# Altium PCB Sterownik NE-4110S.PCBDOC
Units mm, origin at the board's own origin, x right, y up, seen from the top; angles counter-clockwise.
Board outline 196.88 x 218.02 mm, 2 copper layers (TopLayer, BottomLayer); 94 components, 0 nets, 428 pads, 14 vias.
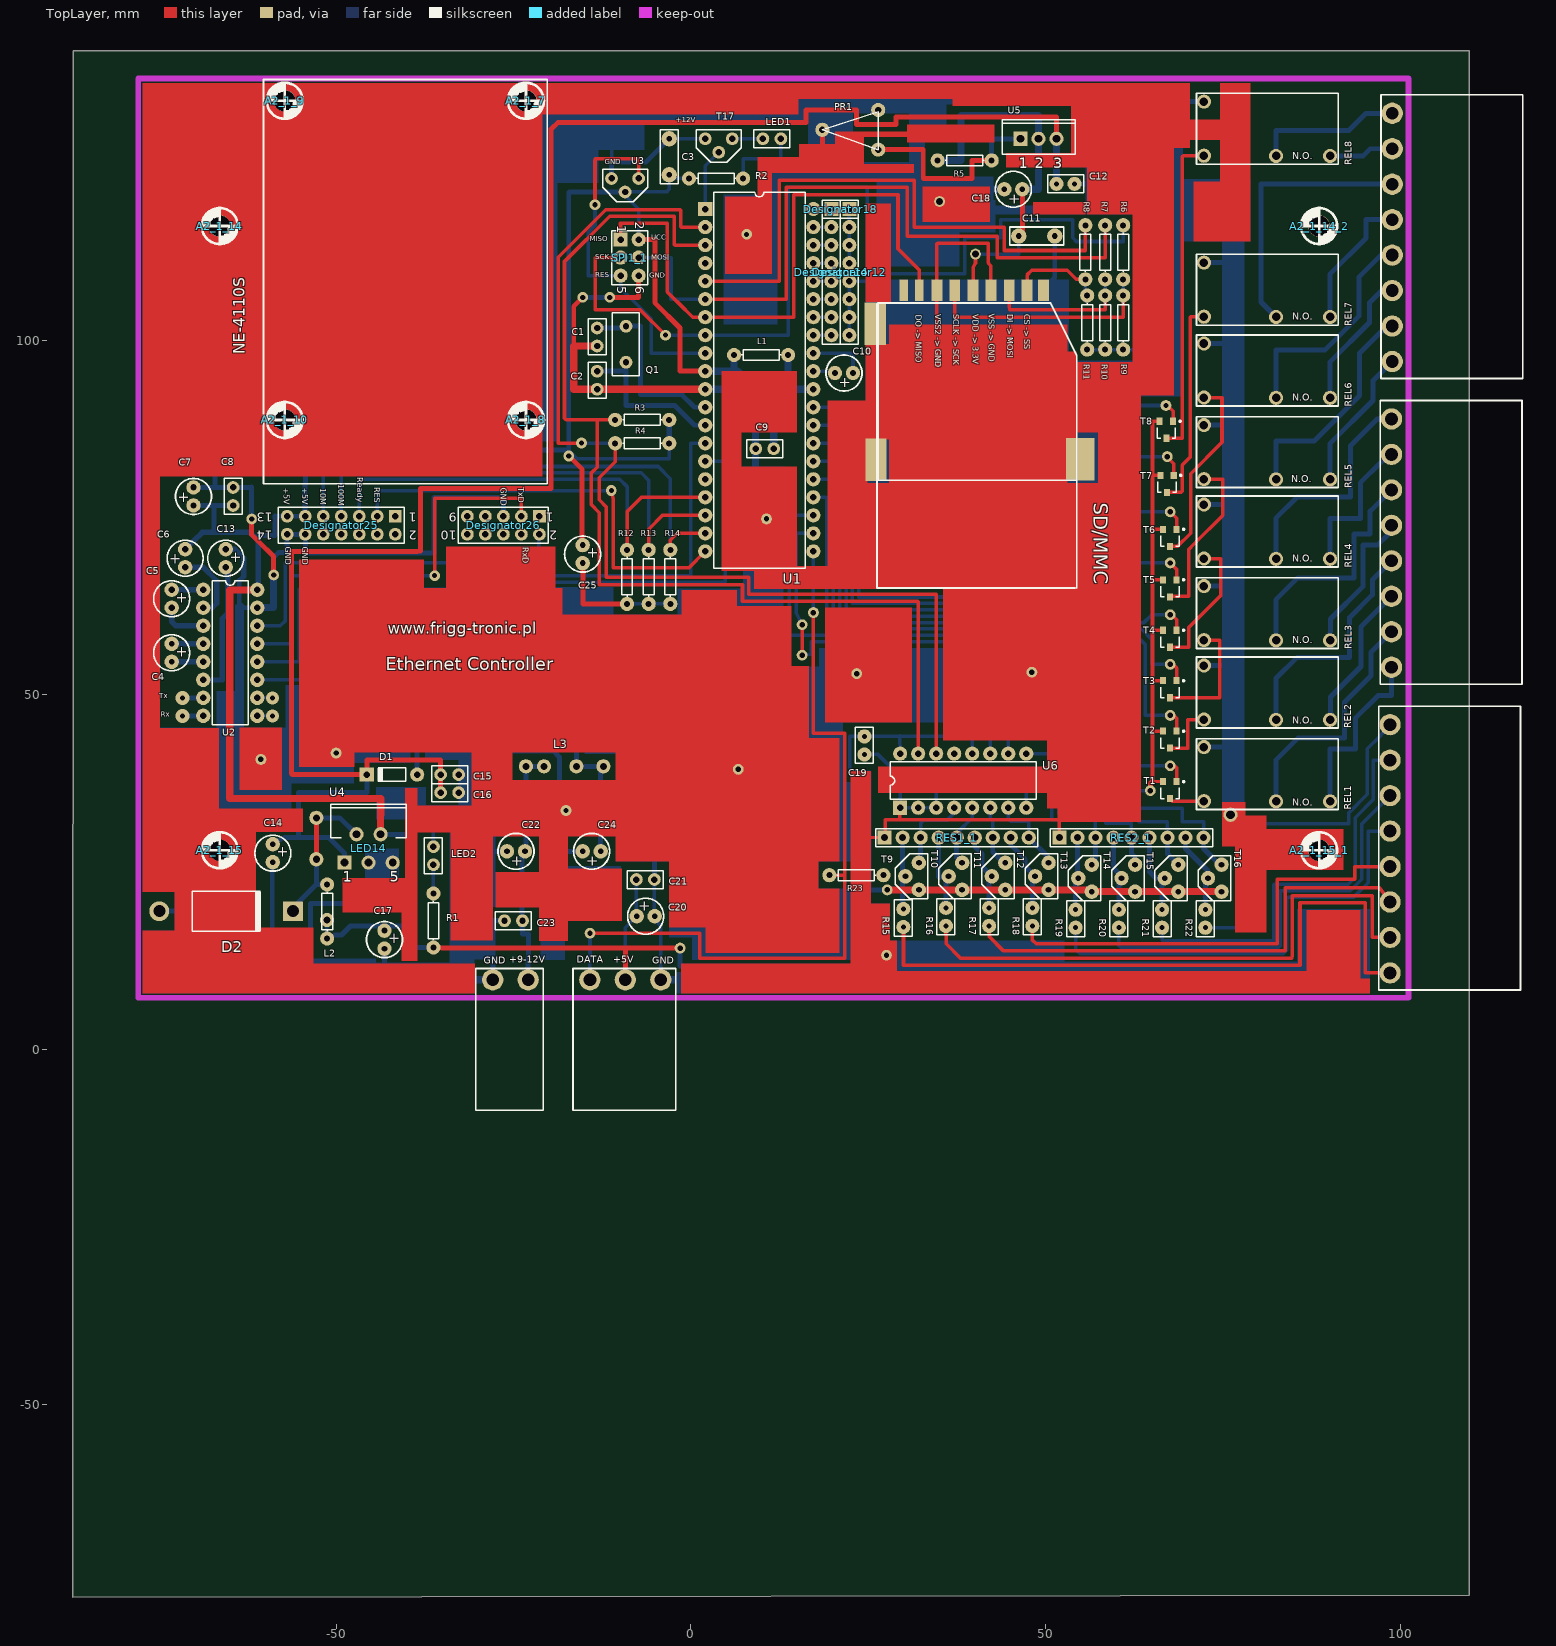
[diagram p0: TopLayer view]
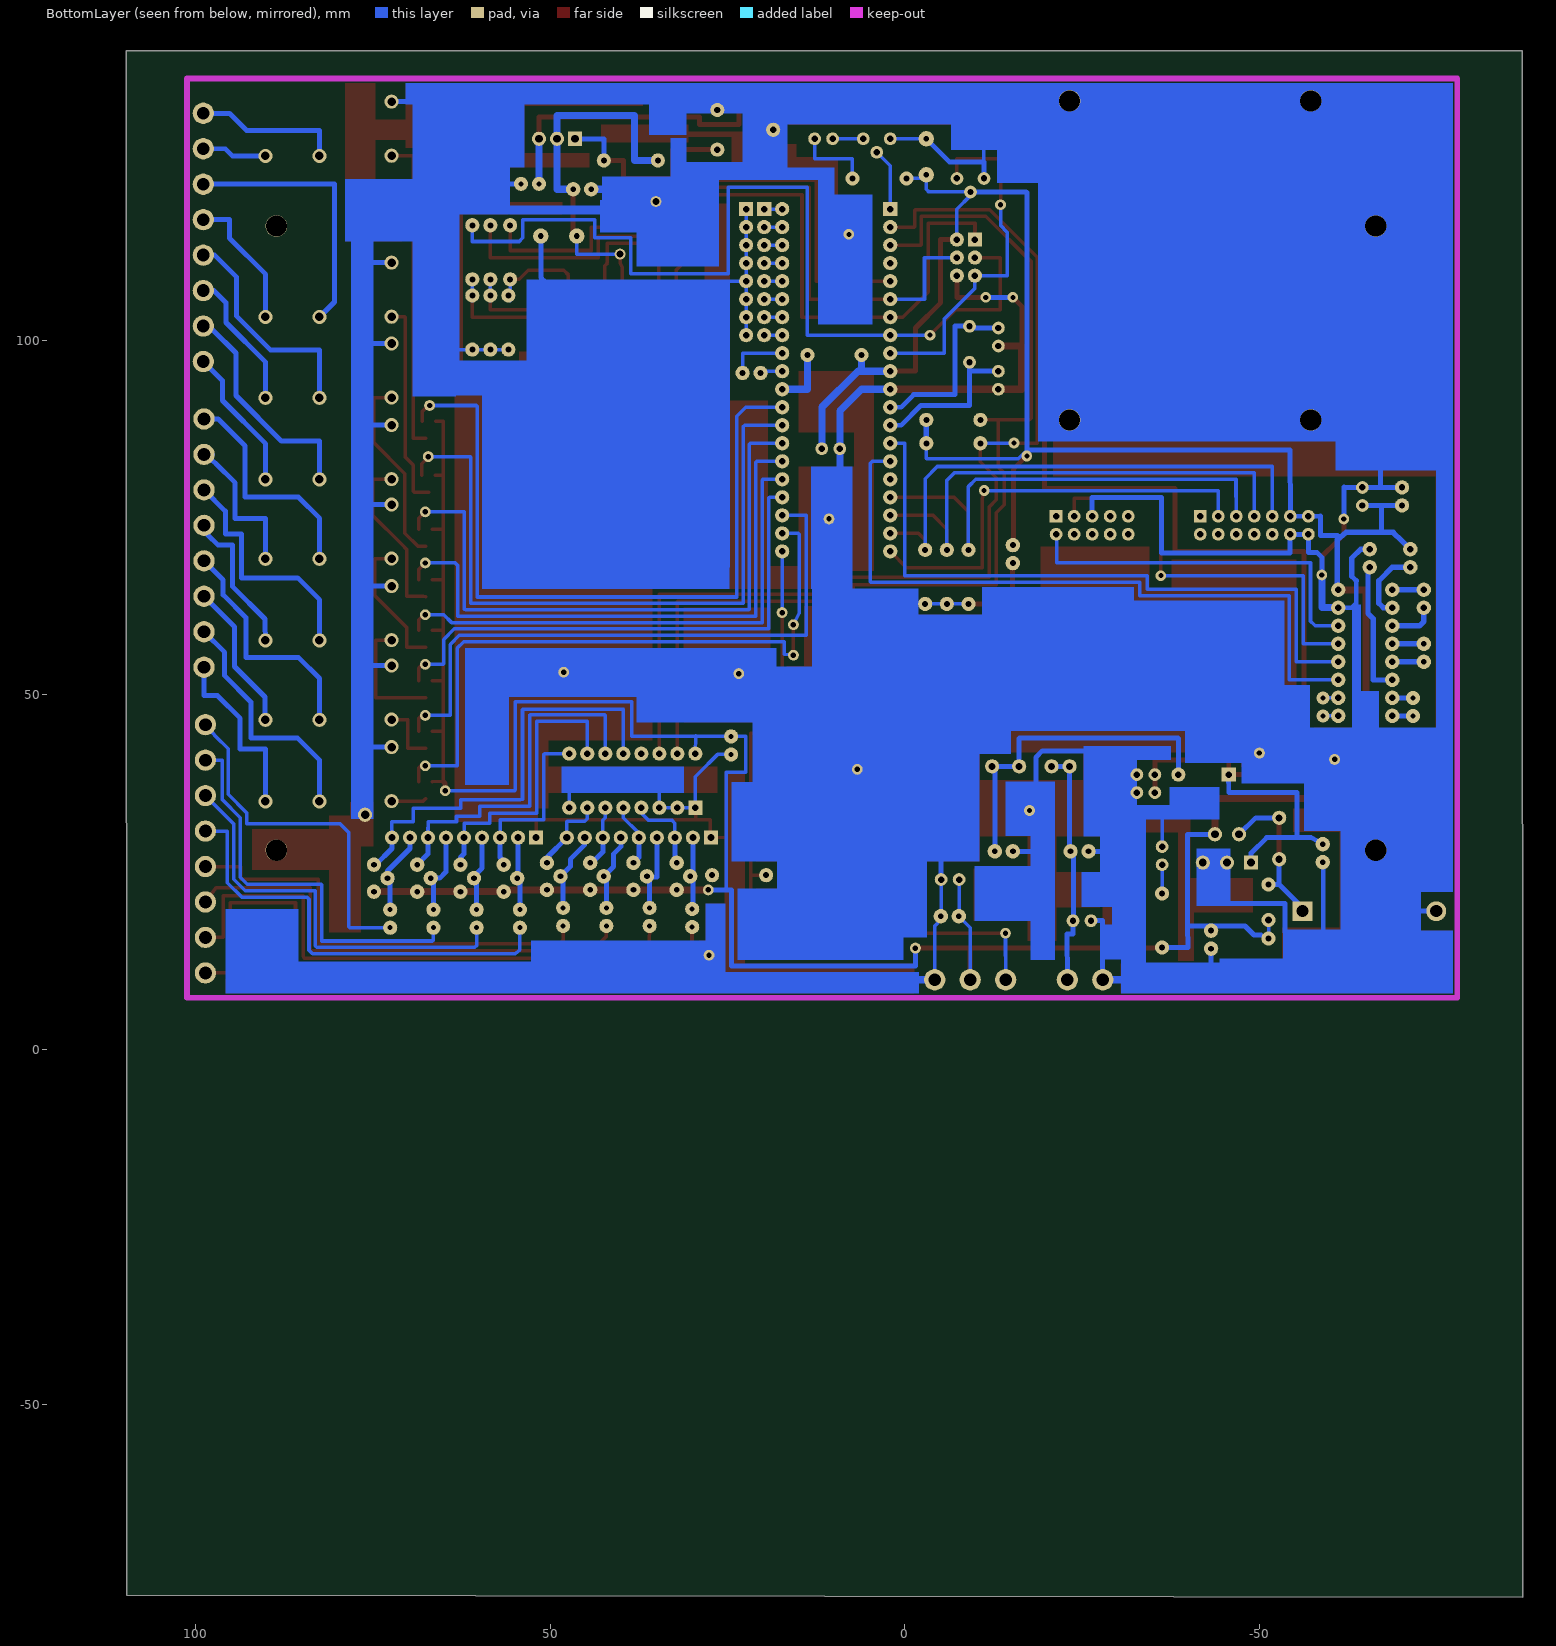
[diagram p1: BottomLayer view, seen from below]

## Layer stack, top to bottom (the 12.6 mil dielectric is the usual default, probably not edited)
TopLayer: signal copper 0.0356
Dielectric: core 0.32, FR-4, Dk 4.8
BottomLayer: signal copper 0.0356

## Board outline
-87.122,-77.216 109.728,-76.962 109.754,140.808 -87.046,140.808

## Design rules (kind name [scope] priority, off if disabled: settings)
Clearance [All] p1: gap=1
ComponentClearance [All] p1: gap=0.254 collisioncheckmode=0
PasteMaskExpansion PasteMaskExpansion_1 [All] p2: expansion=0
PlaneClearance PlaneClearance_1 [All] p1: clearance=0.508
PlaneClearance [All] p2: clearance=0.254
PolygonConnect [All] p1: connectstyle=Relief reliefconductorwidth=0.254 reliefentries=4 polygonreliefangle="90 Angle"
RoutingVias [All] p1: holewidth=1 width=3 viastyle="Through Hole" minholewidth=0.711 minwidth=1.27 maxholewidth=0.711 maxwidth=1.27
ShortCircuit ShortCircuit_1 [All] p2: allowed=FALSE
SolderMaskExpansion SolderMaskExpansion_1 [All] p1: expansion=0.102
SolderMaskExpansion [All] p2: expansion=0.051
TestPointUsage [All] p1: valid=0 allowmultiple=FALSE
Testpoint [All] p1: side=7 testpointundercomponent=TRUE minsize=1.016 maxsize=2.54 preferedsize=1.524 minholesize=0.508 maxholesize=1.016 preferedholesize=0.813 testpointgrid=0.025 style=1001 order=-539222988
UnRoutedNet UnRoutedNet_1 [All] p2:
Width [All] p1: maxlimit=0.8 minlimit=0.7 preferedwidth=0.254 toplayer_maxwidth=0.7 toplayer_prefwidth=0.7 bottomlayer_maxwidth=0.7 bottomlayer_prefwidth=0.5 minimp=50.000000 maximp=50.000000 favimp=50.000000
16 further rules are at their usual default settings.

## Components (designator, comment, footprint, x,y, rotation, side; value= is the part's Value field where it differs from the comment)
A2_1_7 "" S2 -23.24,133.76 r270 top
A2_1_8 "" S2 -23.24,88.76 r270 top
A2_1_9 "" S2 -57.24,133.76 r270 top
A2_1_10 "" S2 -57.24,88.76 r270 top
A2_1_14 "" S2 -66.4,116.1 r270 top
A2_1_14_2 "" S2 88.6,116.1 r270 top
A2_1_15 "" S2 -66.4,28.1 r270 top
A2_1_15_1 "" S2 88.6,28.1 r270 top
C1 "Comment" RAD-0.1#1 -13.194,101.73 r270 top
C2 "Comment" RAD-0.1#1 -13.194,95.634 r270 top
C3 "1u" C2 -3.034,123.32 r90 top
C4 "" CE5#1 -73.178,57.203 r270 top
C5 "" CE5#2 -73.178,64.823 r270 top locked
C6 "" CE5#3 -71.273,67.998 r270 top
C7 "" CE5#2 -70.104,76.708 r90 top
C8 "Comment" RAD-0.1#1 -64.516,76.708 r90 top
C9 "Comment" RAD-0.1#1 11.698,84.712 r180 top
C10 "" CE5#4 22.874,95.38 r0 top
C11 "1u" C2 46.242,114.684 r0 top
C12 "Comment" RAD-0.1#2 54.116,122.05 r180 top
C13 "" CE5#2 -65.558,70.538 r270 top locked
C14 "" CE5#1 -58.928,28.956 r270 top
C15 "Comment" RAD-0.1#1 -32.722,38.762 r180 top
C16 "Comment" RAD-0.1#1 -32.722,36.222 r180 top
C17 "" CE5#1 -43.18,16.764 r270 top
C18 "" CE5#1 46.75,121.288 r180 top
C19 "Comment" RAD-0.1#2 24.484,41.604 r90 top
C20 "" CE5#1 -7.62,18.796 r0 top
C21 "Comment" RAD-0.1#1 -5.122,23.962 r180 top
C22 "" CE5#1 -23.368,27.94 r180 top
C23 "Comment" RAD-0.1#1 -23.722,18.162 r180 top
C24 "" CE5#1 -12.7,27.94 r180 top
C25 "" CE5#1 -15.24,71.12 r270 top
D1 "Comment" DIO7.1-3.9x1.9 -42.12,38.762 r180 top
D2 "Comment" DIO18.84-9.6x5.6 -65.508,19.504 r0 top
Designator12 "Comment" HDR1X8 22.366,118.494 r270 top
Designator14 "Comment" HDR1X8 19.826,118.494 r270 top
Designator18 "Comment" HDR1X2 22.366,118.494 r180 top
Designator25 "Comment" HDR2X7 -41.656,75.184 r180 top
Designator26 "Comment" HDR2X5 -21.336,75.184 r180 top
L1 "Comment" AXIAL-0.3 9.92,97.92 r180 top
L2 "Comment" AXIAL-0.3 -51.264,19.458 r90 top
LED1 "Comment" RAD-0.1#1 12.714,128.4 r180 top
LED2 "Comment" RAD-0.1#1 -36.278,26.062 r90 top
LED14 "Comment" T05D -45.422,28.348 r0 top
Q1 "Comment" RAD-0.2 -9.13,101.978 r270 top
R1 "Comment" AXIAL-0.3 -36.278,18.188 r90 top
R2 "Comment" AXIAL-0.3 3.57,122.812 r180 top
R3 "Comment" AXIAL-0.3 -6.844,88.776 r180 top
R4 "Comment" AXIAL-0.3 -6.844,85.474 r180 top
R5 "Comment" AXIAL-0.3 38.622,125.352 r0 top
R6 "Comment" AXIAL-0.3 60.974,112.398 r270 top
R7 "Comment" AXIAL-0.3 58.434,112.398 r270 top
R8 "Comment" AXIAL-0.3 55.64,112.398 r270 top
R9 "Comment" AXIAL-0.3 60.974,102.492 r270 top
R10 "Comment" AXIAL-0.3 58.434,102.492 r270 top
R11 "Comment" AXIAL-0.3 55.894,102.492 r270 top
R12 "Comment" AXIAL-0.3 -8.976,66.636 r270 top
R13 "Comment" AXIAL-0.3 -5.928,66.636 r270 top
R14 "Comment" AXIAL-0.3 -2.88,66.636 r270 top
R15 "Comment" RAD-0.1#2 29.972,19.812 r270 top
R16 "Comment" RAD-0.1#2 35.976,17.43 r90 top
R17 "Comment" RAD-0.1#2 42.072,17.43 r90 top
R18 "Comment" RAD-0.1#2 48.168,17.43 r90 top
R19 "Comment" RAD-0.1#2 54.264,17.176 r90 top
R20 "Comment" RAD-0.1#2 60.36,17.176 r90 top
R21 "Comment" RAD-0.1#2 66.456,17.176 r90 top
R22 "Comment" RAD-0.1#2 72.552,17.176 r90 top
R23 "Comment" AXIAL-0.3 23.356,24.576 r180 top
RES1_1 "Comment" HDR1X9 27.34,29.876 r0 top
RES2_1 "Comment" HDR1X9 51.978,29.876 r0 top
SPI1_1 "Comment" HDR2X3 -9.886,114.192 r270 top
T1 "Comment" SOT23 67.564,36.576 r180 top
T2 "Comment" SOT23 67.564,43.688 r180 top
T3 "Comment" SOT23 67.564,50.8 r180 top
T4 "Comment" SOT23 67.564,57.912 r180 top
T5 "Comment" SOT23 67.564,65.024 r180 top
T6 "Comment" SOT23 67.564,72.136 r180 top
T7 "Comment" SOT23 67.15,79.756 r180 top
T8 "Comment" SOT23 67.056,87.376 r180 top
T9 "" T#1 32.166,26.32 r270 top
T10 "" T#1 38.262,26.32 r270 top
T11 "" T#1 44.358,26.32 r270 top
T12 "" T#1 50.454,26.32 r270 top
T13 "" T#1 56.55,26.066 r270 top
T14 "" T#1 62.646,26.066 r270 top
T15 "" T#1 68.742,26.066 r270 top
T16 "" T#1 74.838,26.066 r270 top
T17 "" T#2 2.046,128.4 r0 top
U1 "Comment" DIP-40/D53 9.666,94.364 r270 top
U2 "" U16 -68.733,64.823 r270 top locked
U3 "" T#2 -11.162,122.812 r0 top
U5 "Comment" SFM-T3/X1.6V 49.036,128.4 r0 top
U6 "Comment" DIP-16 38.414,37.906 r0 top

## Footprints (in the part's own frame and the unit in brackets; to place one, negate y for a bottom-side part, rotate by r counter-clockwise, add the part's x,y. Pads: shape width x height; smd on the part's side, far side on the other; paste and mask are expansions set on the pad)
AXIAL-0.3 [mm]
  round 2 hole 0.85: 1(-3.81,0) 2(3.81,0)
  silkscreen extent -2.77,-0.76 2.77,0.76
C2 [mil]
  round 85 hole 32: 1(0,0) 2(200,0)
  silkscreen extent -50,-50 250,50
CE5#1 [mil]
  round 80 hole 32: 1(0,0) 2(100,0)
  silkscreen extent -50,-100 150,100
CE5#2 [mil]
  round 80 hole 35.43: 1(0,0) 2(100,0)
  silkscreen extent -50,-100 150,100
CE5#3 [mil]
  round 80 hole 35.43: 1(0,0) 2(-100,0)
  silkscreen extent -150,-100 50,100
CE5#4 [mil]
  round 80 hole 32: 1(0,0) 2(-100,0)
  silkscreen extent -150,-100 50,100
DIO7.1-3.9x1.9 [mm]
  round 2 hole 0.9: 1(-3.55,0)
  rect 2x2 hole 0.9: 2(3.55,0)
  silkscreen extent -1.95,-0.95 2.05,0.95
DIO18.84-9.6x5.6 [mm]
  round 2.8 hole 1.7: 1(-9.42,0)
  rect 2.8x2.8 hole 1.7: 2(9.42,0)
  silkscreen extent -4.8,-2.8 4.9,2.8
DIP-16 [mm]
  rect 2x2 hole 0.9: 1(-8.89,-3.81)
  round 2 hole 0.9: 2(-6.35,-3.81) 3(-3.81,-3.81) 4(-1.27,-3.81) 5(1.27,-3.81) 6(3.81,-3.81) 7(6.35,-3.81) 8(8.89,-3.81) 9(8.89,3.81) 10(6.35,3.81) 11(3.81,3.81) 12(1.27,3.81) 13(-1.27,3.81) 14(-3.81,3.81) 15(-6.35,3.81) 16(-8.89,3.81)
  silkscreen extent -10.3,-2.65 10.3,2.65
DIP-40/D53 [mm]
  rect 2x2 hole 0.9: 1(-24.13,-7.62)
  round 2 hole 0.9: 2(-21.59,-7.62) 3(-19.05,-7.62) 4(-16.51,-7.62) 5(-13.97,-7.62) 6(-11.43,-7.62) 7(-8.89,-7.62) 8(-6.35,-7.62) 9(-3.81,-7.62) 10(-1.27,-7.62) 11(1.27,-7.62) 12(3.81,-7.62) 13(6.35,-7.62) 14(8.89,-7.62) 15(11.43,-7.62) 16(13.97,-7.62) 17(16.51,-7.62) 18(19.05,-7.62) 19(21.59,-7.62) 20(24.13,-7.62) 21(24.13,7.62) 22(21.59,7.62) 23(19.05,7.62) 24(16.51,7.62) 25(13.97,7.62) 26(11.43,7.62) 27(8.89,7.62) 28(6.35,7.62) 29(3.81,7.62) 30(1.27,7.62) 31(-1.27,7.62) 32(-3.81,7.62) 33(-6.35,7.62) 34(-8.89,7.62) 35(-11.43,7.62) 36(-13.97,7.62) 37(-16.51,7.62) 38(-19.05,7.62) 39(-21.59,7.62) 40(-24.13,7.62)
  silkscreen extent -26.5,-6.45 26.5,6.45
HDR1X2 [mm] "Connector; Header; 2 Position"
  rect 1.5x1.5 hole 0.9: 1(0,0)
  round 1.5 hole 0.9: 2(2.54,0)
  silkscreen extent -1.27,-1.27 3.81,1.27
HDR1X8 [mm] "Connector; Header; 8 Position"
  rect 2x2 hole 0.9: 1(0,0)
  round 2 hole 0.9: 2(2.54,0) 3(5.08,0) 4(7.62,0) 5(10.16,0) 6(12.7,0) 7(15.24,0) 8(17.78,0)
  silkscreen extent -1.27,-1.27 19.05,1.27
HDR1X9 [mm] "Connector; Header; 9 Position"
  rect 2x2 hole 1: 1(0,0)
  round 2 hole 1: 2(2.54,0) 3(5.08,0) 4(7.62,0) 5(10.16,0) 6(12.7,0) 7(15.24,0) 8(17.78,0) 9(20.32,0)
  silkscreen extent -1.27,-1.27 21.59,1.27
HDR2X3 [mm]
  rect 2x2 hole 0.9: 1(0,0)
  round 2 hole 0.9: 2(0,2.54) 3(2.54,0) 4(2.54,2.54) 5(5.08,0) 6(5.08,2.54)
  silkscreen extent -1.27,-1.27 6.35,3.81
HDR2X5 [mm] "Connector; Header; 5x2 Position"
  rect 1.8x1.8 hole 0.9: 1(0,0)
  round 1.8 hole 0.9: 2(0,2.54) 3(2.54,0) 4(2.54,2.54) 5(5.08,0) 6(5.08,2.54) 7(7.62,0) 8(7.62,2.54) 9(10.16,0) 10(10.16,2.54)
  silkscreen extent -1.27,-1.27 11.43,3.81
HDR2X7 [mm] "Connector; Header; 7x2 Position"
  rect 1.8x1.8 hole 0.9: 1(0,0)
  round 1.8 hole 0.9: 2(0,2.54) 3(2.54,0) 4(2.54,2.54) 5(5.08,0) 6(5.08,2.54) 7(7.62,0) 8(7.62,2.54) 9(10.16,0) 10(10.16,2.54) 11(12.7,0) 12(12.7,2.54) 13(15.24,0) 14(15.24,2.54)
  silkscreen extent -1.27,-1.27 16.51,3.81
RAD-0.1#1 [mm]
  round 1.8 hole 0.9: 1(0,0) 2(2.54,0)
  silkscreen extent -1.27,-1.27 3.81,1.27
RAD-0.1#2 [mm]
  round 2 hole 0.7: 1(0,0) 2(2.54,0)
  silkscreen extent -1.27,-1.27 3.81,1.27
RAD-0.2 [mm]
  round 1.8 hole 0.9: 1(0,0) 2(5.08,0)
  silkscreen extent -1.91,-1.91 6.98,1.91
S2 [mil]
  round 120 hole 117: 0(0,0)
  silkscreen extent -100,-100 100,100
SFM-T3/X1.6V [mm]
  rect 2x2 hole 1.1: 1(-2.54,0)
  round 2 hole 1.1: 2(0,0) 3(2.54,0)
  silkscreen extent -5.15,-2.2 5.15,2.7
SOT23 [mm] "SOT-23; 3 Leads; Body 3.0 x 2.5 mm, inc. leads (LxW max)"
  rect 0.85x1 smd: 1(-0.95,-1.2) 2(0.95,-1.2) 3(0,1.2)
  silkscreen extent -2.05,-1.32 1.28,1.2
T#1 [mil]
  round 80 hole 32: 1(0,0) 2(75,-75) 3(150,0)
  silkscreen extent -50,-130 200,50
T#2 [mil]
  round 70.87 hole 35.43: 1(0,0) 2(75,-75) 3(150,0)
  silkscreen extent -50,-130 200,50
T05D [mm] "TO, Thru-Hole, Vertical, Heatsink Mounted; 5 Bent Staggered Leads; Pitch 1.7 mm"
  rect 2x2 hole 1.1: 1(-3.4,-2)
  round 2 hole 1.1: 2(-1.7,2) 3(0,-2) 4(1.7,2) 5(3.4,-2)
  silkscreen extent -5.3,1.53 5.3,6.23
U16 [mil]
  round 80 hole 35.43: 1(0,0) 2(100,0) 3(200,0) 4(300,0) 5(400,0) 6(500,0) 7(600,0) 8(700,0) 9(700,300) 10(600,300) 11(500,300) 12(400,300) 13(300,300) 14(200,300) 15(100,300) 16(0,300)
  silkscreen extent -50,50 750,250

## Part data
D1: library part "Diode 1N914"
D2: library part "Diode 1N5402"
Designator12 Designator14: library part "Header 8"
Designator18: library part "Header 2"
Designator25: library part "Header 7X2"
Designator26: library part "Header 5X2"
LED14: library part LM2576HVT-5.0LB03
RES1_1 RES2_1: library part "Header 9"
SPI1_1: library part "Header 3X2"
T1 T2 T3 T4 T5 T6 T7 T8: library part BSS84
U5: library part Diac-NPN

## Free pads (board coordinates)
  round 1.524 hole 0.762: 0(-61.9,74.8) 0(-60.6,40.9) 0(-50,41.8) 0(-14.2,16.4) 0(-1.5,14.3) 0(6.7,39.5) 0(10.682,74.806) 0(15.7,55.6) 0(15.7,59.9) 0(17.3,61.6) 0(23.4,53) 0(27.6,13.3) 0(27.7,22.5) 0(48.1,53.2) 0(64.8,36.5) 0(67,90.8) 0(67.186,83.6) 0(67.6,40) 0(67.6,47.1) 0(67.6,54.3) 0(67.6,61.3) 0(67.6,68.6) 0(67.6,75.8) 1(-58.8,66.9)
  round 2 hole 1: 0(-52.788,26.824) 0(-52.788,32.666) 0(-51.288,18.266) 0(-23.238,39.926) 0(-20.698,39.926) 0(-16.126,39.926) 0(-12.316,39.926)
  round 3 hole 1.8: 0(-27.92,9.832) 0(-22.92,9.832) 0(-14.22,9.832) 0(-9.22,9.832) 0(-4.22,9.832) 0(98.6,10.8) 0(98.6,15.8) 0(98.6,20.8) 0(98.6,25.8) 0(98.6,30.8) 0(98.6,35.8) 0(98.6,40.8) 0(98.6,45.8) 0(98.8,53.9) 0(98.8,58.9) 0(98.8,63.9) 0(98.8,68.9) 0(98.8,73.9) 0(98.8,78.9) 0(98.8,83.9) 0(98.8,88.9) 0(98.9,97) 0(98.9,102) 0(98.9,107) 0(98.9,112) 0(98.9,117) 0(98.9,122) 0(98.9,127) 0(98.9,132)
  rect 3x6 smd: 0(26.016,102.348) 0(26.116,83.148)
  rect 1.2x3 smd: 0(30.016,107.048) 7(32.216,107.048)
  round 1.524 hole 1: 0(35.084,119.562) 0(40.146,112.144)
  rect 1.524x3 smd: 0(49.716,107.048) 1(47.416,107.048) 2(44.916,107.048) 3(42.316,107.048) 4(39.816,107.048) 5(37.216,107.048) 6(34.716,107.048)
  rect 4x6 smd: 0(54.916,83.248)
  round 2 hole 1.2: 1(72.36,35.02) 1(72.36,42.64) 1(72.36,46.52) 1(72.36,54.14) 1(72.36,57.72) 1(72.36,65.34) 1(72.36,69.22) 1(72.36,76.84) 1(72.36,80.42) 1(72.36,88.04) 1(72.36,91.92) 1(72.36,99.54) 1(72.36,103.32) 1(72.36,110.94) 1(72.36,126.02) 1(72.36,133.64) 1(76.1,33.1) 1(82.52,34.98) 1(82.52,46.48) 1(82.52,57.68) 1(82.52,69.18) 1(82.52,80.38) 1(82.52,91.88) 1(82.52,103.28) 1(82.52,125.98) 1(90.14,34.98) 1(90.14,46.48) 1(90.14,57.68) 1(90.14,69.18) 1(90.14,80.38) 1(90.14,91.88) 1(90.14,103.28) 1(90.14,125.98)
  round 2 hole 0.9: 9(18.556,129.67) 10(26.43,132.464) 11(26.43,126.876)

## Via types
v1: diameter 1.524, hole 0.711, TopLayer to BottomLayer, 10 vias
v2: diameter 1.8, hole 0.711, TopLayer to BottomLayer, 2 vias
v3: diameter 2, hole 0.711, TopLayer to BottomLayer, 2 vias

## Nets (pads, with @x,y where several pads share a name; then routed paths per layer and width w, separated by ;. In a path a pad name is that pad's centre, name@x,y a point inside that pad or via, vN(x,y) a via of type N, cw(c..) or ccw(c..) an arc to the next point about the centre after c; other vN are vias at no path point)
pads on no net: A2_1_7.0 A2_1_8.0 A2_1_9.0 A2_1_10.0 A2_1_14.0 A2_1_14_2.0 A2_1_15.0 A2_1_15_1.0 C1.1 C1.2 C2.1 C2.2 C3.1 C3.2 C4.1 C4.2 C5.1 C5.2 C6.1 C6.2 C7.1 C7.2 C8.1 C8.2 C9.1 C9.2 C10.1 C10.2 C11.1 C11.2 C12.1 C12.2 C13.1 C13.2 C14.1 C14.2 C15.1 C15.2 C16.1 C16.2 C17.1 C17.2 C18.1 C18.2 C19.1 C19.2 C20.1 C20.2 C21.1 C21.2 C22.1 C22.2 C23.1 C23.2 C24.1 C24.2 C25.1 C25.2 D1.1 D1.2 D2.1 D2.2 Designator12.1 Designator12.2 Designator12.3 Designator12.4 Designator12.5 Designator12.6 Designator12.7 Designator12.8 Designator14.1 Designator14.2 Designator14.3 Designator14.4 Designator14.5 Designator14.6 Designator14.7 Designator14.8 Designator18.1 Designator18.2 Designator25.1 Designator25.2 Designator25.3 Designator25.4 Designator25.5 Designator25.6 Designator25.7 Designator25.8 Designator25.9 Designator25.10 Designator25.11 Designator25.12 Designator25.13 Designator25.14 Designator26.1 Designator26.2 Designator26.3 Designator26.4 Designator26.5 Designator26.6 Designator26.7 Designator26.8 Designator26.9 Designator26.10 L1.1 L1.2 L2.1 L2.2 LED1.1 LED1.2 LED2.1 LED2.2 LED14.1 LED14.2 LED14.3 LED14.4 LED14.5 Q1.1 Q1.2 R1.1 R1.2 R2.1 R2.2 R3.1 R3.2 R4.1 R4.2 R5.1 R5.2 R6.1 R6.2 R7.1 R7.2 R8.1 R8.2 R9.1 R9.2 R10.1 R10.2 R11.1 R11.2 R12.1 R12.2 R13.1 R13.2 R14.1 R14.2 R15.1 R15.2 R16.1 R16.2 R17.1 R17.2 R18.1 R18.2 R19.1 R19.2 R20.1 R20.2 R21.1 R21.2 R22.1 R22.2 R23.1 R23.2 RES1_1.1 RES1_1.2 RES1_1.3 RES1_1.4 RES1_1.5 RES1_1.6 RES1_1.7 RES1_1.8 RES1_1.9 RES2_1.1 RES2_1.2 RES2_1.3 RES2_1.4 RES2_1.5 RES2_1.6 RES2_1.7 RES2_1.8 RES2_1.9 SPI1_1.1 SPI1_1.2 SPI1_1.3 SPI1_1.4 SPI1_1.5 SPI1_1.6 T1.1 T1.2 T1.3 T2.1 T2.2 T2.3 T3.1 T3.2 T3.3 T4.1 T4.2 T4.3 T5.1 T5.2 T5.3 T6.1 T6.2 T6.3 T7.1 T7.2 T7.3 T8.1 T8.2 T8.3 T9.1 T9.2 T9.3 T10.1 T10.2 T10.3 T11.1 T11.2 T11.3 T12.1 T12.2 T12.3 T13.1 T13.2 T13.3 T14.1 T14.2 T14.3 T15.1 T15.2 T15.3 T16.1 T16.2 T16.3 T17.1 T17.2 T17.3 U1.1 U1.2 U1.3 U1.4 U1.5 U1.6 U1.7 U1.8 U1.9 U1.10 U1.11 U1.12 U1.13 U1.14 U1.15 U1.16 U1.17 U1.18 U1.19 U1.20 U1.21 U1.22 U1.23 U1.24 U1.25 U1.26 U1.27 U1.28 U1.29 U1.30 U1.31 U1.32 U1.33 U1.34 U1.35 U1.36 U1.37 U1.38 U1.39 U1.40 U2.1 U2.2 U2.3 U2.4 U2.5 U2.6 U2.7 U2.8 U2.9 U2.10 U2.11 U2.12 U2.13 U2.14 U2.15 U2.16 U3.1 U3.2 U3.3 U5.1 U5.2 U5.3 U6.1 U6.2 U6.3 U6.4 U6.5 U6.6 U6.7 U6.8 U6.9 U6.10 U6.11 U6.12 U6.13 U6.14 U6.15 U6.16
copper on no net: | length 5563.7
  TopLayer w0.5: v1(-36.1,66.8) -36.1,77.7 -25.9,77.7 -23.9,77.7 -23.876,75.184 ; v1(-15.4,85.5) -18.7,85.5 -18.7,86 -18.7,111.7 -12,118.4 -11.4,118.4 -1.5,118.4 -1.4,118.3 -1.4,116.1 -1.4,116.008 -1.346,115.954 2.046,115.954 ; -14.2,16.4 -0.1,16.4 1.3,16.4 1.3,12.9 21.7,12.9 21.7,44.6 17.3,44.6 17.3,61.6 ; v1(-13.5,119.1) -13.5,125.3 -13.448,125.606 -7.352,125.606 -7.352,122.812 ; -13.2,88.776 -13.2,82.1 -14,81.3 -14,76.8 -12.9,75.7 -12.9,65.5 0.4,65.5 7.3,65.5 7.3,63.2 24,63.2 32,63.2 32.064,63.136 32.064,41.716 ; v1(-11.2,78.8) -10.9,77.7 -10.9,67.9 -0.3,67.9 2.046,70.234 ; -10.654,85.474 -10.654,82.846 -12.9,80.6 -12.9,77.5 -11.9,76.5 -11.9,66.6 1.1,66.6 8.2,66.6 8.2,64.2 34.6,64.2 34.604,54.996 34.604,41.716 ; -10.654,88.776 -17.576,88.776 -17.8,89 -17.8,111.1 -11.4,117.5 -2.5,117.5 -2.3,117.5 -2.3,113.5 -2.214,113.414 2.046,113.414 ; -9.886,111.652 -13.448,111.636 -13.448,111.414 -13.448,104.27 -7.098,104.27 ; -9.886,114.192 -9.9,116.5 -3.3,116.5 -3.288,106.81 ; -8.976,70.446 -8.976,75.824 -6.946,77.854 2.046,77.854 ; -7.606,104.27 -7.098,104.27 ; -5.928,70.446 -5.928,73.372 -3.986,75.314 2.046,75.314 ; v1@-4.05,100.714 v1(-3.542,100.714) -7.098,104.27 ; -2.88,70.446 -2.88,71.82 -1.926,72.774 2.046,72.774 ; -0.748,104.27 -3.288,106.81 ; 1.792,103.254 0.268,103.254 -3.288,106.81 ; 2.046,103.254 14.492,103.254 14.492,120.526 29.224,120.526 29.224,112.906 32.216,109.914 32.216,107.048 ; 2.046,105.794 11.952,105.794 13.476,105.794 13.476,121.542 30.494,121.542 30.494,114.684 43.194,114.684 43.194,111.636 58.434,111.636 58.434,116.208 ; 2.046,108.334 8.904,108.334 12.46,108.334 12.46,122.558 31.51,122.558 31.51,115.954 44.21,115.954 44.21,112.652 55.64,112.652 55.64,116.208 ; 15.7,55.6 15.7,60.3 15.7,59.9 ; 19.546,24.576 21.676,24.576 ; 24.8,29.9 27.34,29.876 ; 27.4,29.936 27.4,32.4 51.8,32.4 51.978,32.222 51.978,29.876 ; 29.5,32.4 29.524,34.096 ; 29.5,34.072 29.7,34.272 29.7,34.3 ; 29.972,17.272 30,16.2 30,11.9 85.7,11.9 85.9,11.9 85.9,20.7 95.1,20.7 95.1,10.8 98.6,10.8 ; 34.716,101.318 34.716,107.048 34.716,113.572 34.812,113.668 41.924,113.668 41.924,110.896 42.316,110.504 42.316,107.048 ; 34.812,98.428 34.812,101.222 ; 35.976,17.43 36,14.9 38,12.9 84.7,12.9 84.8,13.2 84.8,15.8 84.8,21.7 96.1,21.7 96.1,15.8 98.6,15.8 ; 37.216,107.048 37.216,103.626 37.352,103.254 60.974,103.254 60.974,103.762 60.974,106.302 ; 39.816,107.048 39.816,110.29 40.146,110.874 40.146,112.144 ; 42.072,17.43 42.072,15.928 44.1,13.9 83.6,13.9 83.8,13.9 83.8,20.4 83.8,22.8 97.1,22.8 98.6,20.8 ; 44.916,107.048 44.916,104.834 44.972,104.27 52.338,104.27 58.434,104.27 58.434,106.302 ; 47.416,107.048 47.416,109.192 48.082,109.858 53.1,109.858 54.37,108.588 55.64,108.588 ; 48.168,17.43 48.168,15.432 48.7,14.9 82.5,14.9 82.7,14.9 82.7,23.7 82.7,24 93.6,24 93.6,25.8 98.6,25.8 ; 65.1,52 66.614,52 ; 65.112,44.888 66.614,44.888 ; 65.112,59.112 66.614,59.112 ; 65.156,80.956 66.2,80.956 ; 65.176,66.224 66.614,66.224 ; 65.236,73.336 66.614,73.336 ; 66.106,88.576 65.1,88.6 65.1,65.3 65.1,54.9 65.1,43.4 65.1,37.8 66.614,37.776 ; 67,90.8 67.2,90.8 68.006,89.994 68.006,88.576 ; 67.15,78.556 69.156,78.556 69.3,78.7 69.3,82.4 70.4,83.5 70.4,103.2 70.52,103.32 72.36,103.32 ; 67.186,83.6 67.186,83.5 68.1,82.586 68.1,80.956 ; 67.564,35.376 67.92,35.02 68.68,35.02 72.36,35.02 ; 67.564,42.488 70.088,42.488 70.1,42.5 70.1,46.5 70.12,46.52 72.36,46.52 ; 67.564,49.6 70,49.6 70.4,49.6 74.6,49.6 74.6,57.7 72.36,57.72 ; 67.564,56.712 70.188,56.712 70.2,56.724 70.2,59.5 74.7,64 74.7,69.2 73.4,69.2 72.36,69.22 ; 67.564,63.824 67.9,63.9 70.2,63.9 70.2,70.5 71,71.3 75,75.3 75,80.4 73.4,80.4 72.36,80.42 ; 67.564,70.936 68.636,70.936 70.5,72.8 70.5,81.2 74.9,85.6 74.9,91.9 74.88,91.92 72.36,91.92 ; 67.564,86.176 69.3,86.176 69.3,125.9 69.42,126.02 70.1,126.02 72.36,126.02 ; 67.6,40 68.2,40 68.5,39.7 68.514,37.776 ; 67.6,47.1 68.1,47.1 68.514,46.686 68.514,44.888 ; 67.6,54.3 68,54.3 68.514,53.786 68.514,52 ; 67.6,61.3 67.8,61.3 68.514,60.586 68.514,59.112 ; 67.6,68.6 68.514,67.686 68.514,66.224 ; 67.6,75.8 68.514,74.886 68.514,73.336
  TopLayer w0.7: -61.9,74.8 -61.9,72.6 -60.9,71.6 -58.8,69.5 -58.8,66.9 ; -52.788,26.824 -52.788,32.666 ; -36.278,14.378 -35.1,14.3 -9.22,14.3 -9.22,9.832 ; -35.3,40.8 -45.676,40.794 -45.67,38.762 -56.162,38.762 -56.3,38.9 -56.3,70.2 -38.6,70.2 -38.1,70.3 -38.1,79.1 -19.7,79.1 -19.7,129.8 -18.714,130.686 16.27,130.686 16.27,132.464 23.382,132.464 23.382,130.432 28.97,130.432 28.97,131.448 51.576,131.448 51.576,128.4 ; -35.262,36.222 -35.262,40.794 ; v1(-17.2,83.7) -15.3,81.8 -15.3,71.9 -15.24,71.12 ; -16.496,99.19 -16.496,104.778 v1(-15.226,106.048) ; -15.24,68.58 -15.2,67.3 -15.2,62.8 -8.976,62.826 ; v1(-11.416,106.048) -7.352,106.048 -7.352,109.106 ; -9.5,14.3 -1.5,14.3 ; -7.346,114.192 -5.066,114.176 -5.066,105.286 -1.51,101.73 -1.51,95.634 2.046,95.634 ; 18.556,126.876 18.556,129.67 ; 26.43,126.876 32.78,126.876 32.78,122.812 39.638,122.812 39.638,125.352 42.432,125.352 ; 27.34,29.876 27.4,29.936 ; 45.734,114.684 46.75,115.192 46.75,116.97 46.75,121.288 ; 56.296,22.51 56.55,22.256 ; 64.8,36.5 64.8,37.5 65.1,37.8
  TopLayer w1: -61.113,64.823 -62,64.8 -65,64.8 -65,44.7 -65,35.4 -43.7,35.4 -43.722,30.348 ; -13.194,99.19 -16.496,99.19 -16.496,93.094 2.046,93.094 ; 27.7,22.5 32.166,22.51 38.262,22.51 50.454,22.51 56.296,22.51 ; 56.55,22.256 68.742,22.256 74.838,22.256 75.1,22.2
  BottomLayer w0.5: -72.304,19.504 -72.1,19.3 ; -61.113,47.043 v2@-58.985,47.043 ; -61.113,49.583 v2@-58.985,49.583 ; -61.113,52.123 -54.777,52.123 -54.223,52.123 -54.2,52.146 -54.2,52.7 -54.2,64 -33.1,64 -33.1,65.9 4.8,65.9 4.84,65.94 4.84,68.456 4.84,82.68 4.586,82.934 2.046,82.934 ; -61.113,54.663 -55.237,54.663 -55.2,54.7 -55.2,56.3 -55.2,64.9 -53.3,64.9 -34.2,64.9 -34.2,66.8 -9.1,66.8 0,66.8 ; -61.113,57.203 -56.2,57.2 -56.2,58 -56.2,62.7 -56.2,66.8 -42,66.8 -39.8,66.8 v1(-36.1,66.8) ; -61.113,59.743 -57.857,59.743 -57.8,59.8 -57.2,60.4 -57.2,67.8 -57.2,68.6 -23.4,68.6 -21.4,68.6 -21.4,71.7 -21.336,72.644 ; -51.816,75.184 -51.8,82.2 -49.6,82.2 -4.6,82.2 -2.88,80.48 -2.88,70.446 ; -51.288,18.266 -51.288,15.672 -51.264,15.648 ; -49.276,75.184 -49.3,81.3 -47.8,81.3 -7,81.3 -5.928,80.228 -5.928,70.446 ; -46.736,75.184 -46.7,80.4 -44.9,80.4 -10,80.4 -8.976,79.376 -8.976,70.446 ; -44.196,75.184 -44.2,78.8 -42.7,78.8 v1(-11.2,78.8) ; -36.278,21.998 -36.278,26.062 ; -36.278,28.602 -36.278,33.428 ; -33.2,9.5 -32.868,9.832 ; -27.92,9.832 -27.902,9.85 ; -23.2,10.9 -22.9,8.9 ; -17.2,84.5 -16,83.3 -3.3,83.3 -3.068,83.3 -3.034,83.334 -3.034,85.474 ; -15.7,120.9 -15.693,120.907 ; v1(-15.4,85.5) -10.68,85.5 -10.654,85.474 ; -14.22,9.832 -14.2,16.4 ; v1(-13.5,119.1) -13.5,116.2 -14.464,115.192 -14.464,109.35 -14.448,109.112 -9.886,109.112 -9.892,107.318 -7.352,104.778 -5.574,103 -5.574,98.174 2.046,98.174 ; -11.162,122.812 -11.162,127.738 -10.6,128.3 ; -9.5,10.9 -9.2,8.9 ; -9.22,9.832 -9.22,17.18 -7.62,18.78 -7.62,18.796 -7.662,18.838 -7.662,23.962 ; -8.976,62.826 -2.88,62.826 -2.806,62.9 7.3,62.9 7.7,63 7.7,65.1 ; -7.346,111.652 -2.78,111.636 -2.78,105.794 2.046,105.794 ; -7.346,114.192 -7.346,118.488 -9.257,120.399 -9.257,120.907 -3.415,120.907 -3.034,121.288 -3.034,123.32 ; -5.122,23.962 -5.122,18.838 -5.08,18.796 -5.08,18.28 -4.22,17.42 -4.22,9.832 ; v1(-3.542,100.714) 2.046,100.714 13.73,100.714 13.73,121.542 24.906,121.542 24.906,109.35 38.622,109.35 38.622,114.43 43.702,114.43 43.702,116.97 53.862,116.97 53.862,114.43 54.37,113.922 60.974,113.922 60.974,116.208 ; -3.034,122.812 -0.24,122.812 ; -3.034,128.4 2.046,128.4 ; -1.268,9.832 -1.2,9.9 ; 0,66.9 0,66.8 ; 2.046,85.474 0,85.5 0,66.8 ; 2.046,118.494 2.046,124.59 3.951,126.495 ; 5.856,128.4 10.174,128.4 ; 7.38,122.812 7.38,125.606 12.714,125.606 12.714,128.4 ; 15.7,55.6 17,55.7 17,57.5 35.3,57.5 55.1,57.5 62.2,57.5 63.1,56.6 63.1,48.3 63.1,40 67.6,40 ; 15.7,59.9 14.9,61.5 14.9,66.8 14.9,72.648 15.026,72.774 17.286,72.774 ; 17.2,61.7 17.286,61.786 17.286,70.234 ; 17.286,75.314 17.272,75.3 13.9,75.3 13.9,65.6 13.9,59.9 13.9,58.4 17.8,58.4 42.8,58.4 58.8,58.4 62.8,58.4 64.1,57.1 64.1,53.1 64.1,47.1 65.1,47.1 67.6,47.1 ; 17.286,77.854 19.054,77.854 19.2,77.8 19.2,59.3 19.9,59.3 53.9,59.3 61.9,59.3 63.5,59.3 65,57.8 65,54.4 65.1,54.3 67.6,54.3 ; 17.286,80.394 19.994,80.394 20.1,80.288 20.1,60.2 20.8,60.2 58.1,60.2 63.9,60.2 65,61.3 67.6,61.3 ; 17.286,82.934 20.866,82.934 21,82.8 21,61.1 22.6,61.1 36.4,61.1 50.3,61.1 63,61.1 ; 17.286,85.474 21.774,85.474 21.9,85.348 21.9,62.1 22,62 23.4,62 61.9,62 62.1,62.1 62.1,75.8 67.6,75.8 ; 17.286,88.014 22.586,88.014 22.8,87.8 22.8,62.9 22.9,62.9 23.4,62.9 61.2,62.9 61.2,83.5 61.3,83.6 67.186,83.6 ; 17.286,90.554 22.446,90.554 23.7,89.3 23.7,63.8 60.3,63.8 60.3,90.7 60.4,90.8 67,90.8 ; 17.286,95.634 21.096,95.634 ; 17.286,98.174 22.874,98.174 22.874,95.38 ; 17.286,100.714 19.826,100.714 ; 17.286,103.254 19.826,103.254 ; 17.286,105.794 19.826,105.794 ; 17.286,108.334 19.826,108.334 ; 17.286,110.874 19.826,110.874 ; 17.286,113.414 19.826,113.414 ; 17.286,115.954 19.826,115.954 ; 17.286,118.494 19.826,118.494 ; 22.366,100.714 22.366,118.494 ; 22.366,108.334 25.16,108.334 ; 24.484,41.604 26.4,41.6 29.096,38.904 29.524,38.476 29.524,34.096 34.604,34.096 34.604,36.496 34.608,36.5 47.2,36.5 47.304,36.396 47.304,34.096 ; 25.3,22.5 25.2,22.6 25.2,39.1 22.4,39.1 22.4,44.1 22.444,44.144 24.484,44.144 26.756,44.144 29.5,44.2 ; 29.524,41.716 29.524,41.764 29.5,44.2 ; 32.42,29.876 32.42,31.92 32.8,32.3 36.1,32.3 37.144,33.344 37.144,34.096 ; 37.5,29.876 37.6,30.6 39.7,32.7 39.684,34.096 ; 39.684,41.716 39.684,47.984 39.7,48 53.8,48 53.9,47.9 53.9,35.3 54.2,35.2 62.6,35.2 62.6,34 65.1,34 69.3,34 69.3,32.1 72.3,32.1 72.298,29.876 ; 40.146,112.144 45.734,112.144 46.242,112.144 46.242,112.652 46.242,114.684 ; 42.224,34.096 42.224,32.676 42.58,32.32 42.58,29.876 ; 42.224,41.716 42.224,47.124 42.3,47.2 52.8,47.2 52.9,47.1 52.9,34.3 59.9,34.3 59.9,32.9 63.2,32.9 63.2,32.1 67.2,32.1 67.218,30.682 67.218,29.876 ; 44.764,34.096 44.764,32.536 45.1,32.2 47.6,32.2 47.66,32.14 47.66,29.876 ; 44.764,41.716 44.764,46.264 44.8,46.3 45.2,46.3 51.9,46.3 51.9,46.1 51.9,33.3 58.5,33.3 58.5,31.9 62.1,31.9 62.138,29.876 ; 47.304,41.716 50.784,41.716 50.9,41.6 50.9,33.4 50.9,32.4 57.058,32.4 57.058,29.876 ; 54.264,17.176 54.264,14.036 54.9,13.5 83.5,13.5 84,14 84,21.2 84.3,21.5 93.5,21.5 95.5,23.5 95.5,30.8 95.7,30.8 98.6,30.8 ; 55.64,105.794 55.64,105.54 55.64,108.588 ; 55.64,116.208 55.894,116.208 ; 55.894,98.682 63.006,98.682 ; 58.434,105.794 58.434,105.54 58.434,108.588 ; 60.36,17.176 60.36,14.66 60.62,14.4 82.9,14.4 83.1,14.6 83.1,21.8 83.1,22.4 93,22.4 94.6,24 94.6,31.8 95.7,32.9 98.6,35.8 ; 60.974,105.794 60.974,105.54 60.974,108.588 ; 63,61.2 63,61.1 ; 64.8,36.5 55,36.5 54.9,36.6 54.9,49 38.5,49 38.5,44.2 38.444,44.144 29.5,44.2 ; 66.456,17.176 66.456,15.444 66.6,15.3 82.2,15.3 82.2,23.2 82.3,23.3 92.7,23.3 93.7,24.3 93.7,32.7 96.2,35.2 96.2,40.8 98.6,40.8 ; 67.6,68.6 63.4,68.6 63,68.2 63,61.1 ; 72.552,17.176 78.276,17.176 78.4,17.3 78.4,30.6 79.6,31.8 92.8,31.8 92.8,33.4 95.4,36 95.4,42.4 97.1,44.1 98.6,45.8
  BottomLayer w0.7: -74.928,19.504 -72.304,19.504 ; -73.432,43.202 -65.812,43.202 ; v3(-71.654,47.012) -68.764,47.012 ; v3(-71.654,49.552) -68.764,49.552 ; -71.431,70.38 -71.273,70.538 ; -70.104,76.708 -64.516,76.708 ; -70.104,79.248 -64.516,79.248 -62.048,79.248 -61.9,79.3 -61.9,74.8 ; -68.733,52.123 -66.32,52.092 ; -67.2,73.02 -67.2,76.708 ; -67.1,79.248 -67.1,82.4 ; -63.653,66.093 -63.653,62.887 -63.049,62.283 -61.113,62.283 ; -60.986,71.904 -61,69.1 -61,71.9 -61,72.5 -58.6,72.5 -58.6,75.2 -54.356,75.184 -54.3,84.5 -53.28,84.5 -17.2,84.5 -17.2,85.8 -17.2,120.8 -17.093,120.907 -9.257,120.907 ; -59.646,43.334 -58.884,44.096 ; -58.928,26.416 -59,25.3 -59,16.8 -59.138,15.24 -56.344,12.346 -55.836,12.854 ; -58.928,28.956 -57.3,29.9 -55.7,29.9 -55.328,29.872 ; -58.8,66.9 -58.8,69.4 -58.1,70.1 -56.9,70.1 -56.896,72.644 -54.356,72.644 -54.3,71.6 -54.3,70 ; -56.344,19.734 -52.788,23.268 ; -53.6,16.6 -53.6,20.6 -53.1,20.6 -48.7,20.6 -41.8,20.6 -45.422,21.744 -45.422,26.348 -42.022,26.348 ; -53,70 -54.3,70 ; -52.788,26.824 -52.788,23.268 ; -52.788,32.666 -49.486,32.666 -47.122,30.348 ; -50.248,16.156 -49.232,16.156 -47.962,17.426 -45.168,17.426 -39.834,17.426 ; -48.822,26.348 -48.822,27.684 -51.01,29.872 -55.328,29.872 ; -45.67,38.762 -45.676,36.222 -48.978,36.222 -55.328,36.222 -55.328,33.682 -55.328,29.872 ; -43.722,30.348 -39.834,30.348 -39.834,17.426 ; -43.2,12.3 -43.18,14.224 ; -38.57,38.762 -38.57,42.47 -38.57,43.83 -38.5,43.9 -37.1,43.9 -17.4,43.9 -16.2,43.9 -16.126,43.826 -16.126,42.626 -16.126,39.926 -12.316,39.926 -12.7,39.542 -12.7,27.94 ; -36.278,14.378 -39.9,14.4 -39.834,17.426 ; -30.9,27.9 -26.006,27.9 ; -28.4,40.6 -28.4,41.3 -27.6,42.1 -19.4,42.1 -18.5,41.2 -18.5,28 -18.44,27.94 -15.24,27.94 ; -27.902,9.85 -27.902,18.162 -26.262,18.162 ; -26.416,75.184 -26.4,77.8 -36.2,77.8 -36.2,70 -54.3,70 ; -23.762,18.162 -23.762,27.738 -23.238,27.988 -23.238,39.926 -20.698,39.926 ; -23.722,18.162 -23.7,16.3 -22.9,16.3 -22.92,9.832 ; v1(-15.226,106.048) v1(-11.416,106.048) ; -13.194,95.634 -9.13,95.634 -9.13,96.898 -9.13,94.364 -9.13,90.808 -2.272,90.808 0.522,88.014 2.046,88.014 ; -13.194,101.73 -9.892,101.73 -9.13,101.978 -7.098,101.984 -7.098,96.904 -7.098,92.332 -1.256,92.332 0.522,90.554 2.046,90.554 ; -11.162,122.812 -11.162,125.098 -6.336,125.098 -3.034,128.4 ; -5.122,23.962 -5.122,26.378 -5.1,26.4 ; -1.5,14.3 -1.5,11.8 24.4,11.8 24.4,22.5 25.3,22.5 27.7,22.5 ; 29.88,19.716 29.88,24.034 30.261,24.415 ; 29.88,29.876 29.88,24.796 29.626,24.288 30.134,24.288 ; 32.166,26.32 32.166,26.574 32.42,26.828 32.42,29.876 ; 34.96,29.876 34.96,24.288 35.722,24.288 36.23,24.288 ; 35.976,19.97 35.976,24.034 36.357,24.415 ; 37.5,29.876 37.5,28.098 37.5,27.082 38.262,26.32 ; 38.114,119.002 40.654,119.002 ; 40.04,29.876 40.04,28.606 41.056,27.59 41.056,25.812 42.453,24.415 42.072,24.034 42.072,19.97 ; 41.818,24.288 42.326,24.288 ; 42.522,125.098 42.432,125.606 42.432,128.4 46.496,128.4 ; 42.58,29.876 42.58,27.844 44.104,26.32 ; 45.12,29.876 45.12,28.86 47.152,26.828 47.152,25.812 48.549,24.415 48.168,24.034 48.168,19.97 ; 47.66,29.876 50.454,27.082 50.454,26.32 ; 47.914,24.288 48.422,24.288 ; 50.814,94.618 50.814,108.334 51.322,108.842 51.322,114.684 ; 50.814,97.92 50.816,108.348 ; 51.576,128.4 51.666,128.49 ; 54.01,24.034 54.518,24.034 ; 54.116,122.05 55.894,122.05 ; 54.264,19.716 54.264,23.78 54.645,24.161 ; 54.518,24.288 54.518,29.876 ; 56.55,26.066 56.55,26.574 57.058,27.082 57.058,29.876 ; 59.598,29.876 59.598,25.558 60.741,24.415 60.741,24.161 60.36,23.78 60.36,19.716 ; 60.106,24.034 60.614,24.034 ; 62.138,29.876 62.138,27.59 62.646,27.082 62.646,26.066 ; 64.678,29.876 64.678,25.05 65.567,24.161 66.837,24.161 66.456,23.78 66.456,19.716 ; 66.202,24.034 66.71,24.034 ; 67.218,29.876 67.218,27.59 68.742,26.066 ; 67.5,133.6 67.54,133.64 72.36,133.64 ; 69.758,29.876 69.758,28.352 72.933,25.177 72.933,24.161 72.552,23.78 72.552,19.716 ; 72.298,24.034 72.806,24.034 ; 72.298,29.876 72.298,28.352 74.584,26.066 74.838,26.066 ; 72.36,42.64 75.24,42.64 75.3,42.7 75.3,54.2 ; 72.36,54.14 75.26,54.14 ; 72.36,65.34 75.24,65.34 ; 72.36,76.84 75.14,76.84 ; 72.36,88.04 75.26,88.04 ; 72.36,99.54 75.16,99.54 ; 72.36,110.94 75.24,110.94 ; 74.838,22.256 75.346,22.256 ; 75.4,44.3 75.4,122 ; 82.52,34.98 82.5,40.8 85.6,43.9 92.2,43.9 92.2,45 92.2,49 95.9,52.7 95.9,56 98.8,58.9 ; 82.52,46.48 82.5,46.8 82.5,52.3 85.5,55.3 92.9,55.3 92.9,60.9 96.1,64.1 96.1,66.2 98.8,68.9 ; 82.52,57.68 82.5,58.8 82.5,63.4 85.6,66.5 93.5,66.5 93.5,72.7 95.8,72.7 95.8,75.9 98.8,78.9 ; 82.52,69.18 82.5,74.9 85.5,77.9 93,77.9 93,85.1 96.8,88.9 98.8,88.9 ; 82.52,80.38 82.5,85.8 87.9,85.8 94.3,92.2 94.3,98.2 97.6,101.5 98.9,102 ; 82.52,91.88 82.5,98.6 89.4,98.6 94.2,103.4 94.2,108.9 97.3,112 98.9,112 ; 82.52,103.28 80.4,105.4 80.4,122 90.5,122 98.9,122 ; 82.52,125.98 82.5,129.6 92.8,129.6 95.2,132 95.3,132 98.9,132 ; 90.14,34.98 90.1,42.4 93.7,42.4 93.7,46.7 96.9,49.9 98.8,49.9 98.8,51.3 98.8,53.9 ; 90.14,46.48 90.2,47.7 90.2,49.7 94.5,54 94.5,59.6 98.8,63.9 ; 90.14,57.68 90.2,60 90.2,60.7 94.8,65.3 94.8,71.1 96.8,71.1 98.3,72.6 98.8,73.9 ; 90.14,69.18 90.1,74.9 94.4,74.9 94.4,79.9 97.1,82.6 98.8,83.9 97.6,83.9 ; 90.14,80.38 90.1,85.4 96.2,91.5 96.2,94.3 98.9,97 ; 90.14,91.88 90.1,96.9 95.7,102.5 95.7,105.3 97.4,107 98.9,107 ; 90.14,103.28 90.1,109.3 95.2,114.4 95.2,117 95.8,117 98.9,117 ; 90.14,125.98 94.8,126 95.8,127 98.9,127 97.9,127 ; -52.788,23.268 -51.264,23.268 -52.788,23.268 ; 44.104,26.32 44.358,26.32 44.104,26.32
  BottomLayer w0.762: -73.178,54.663 -68.733,54.663 ; -73.178,57.203 -68.733,57.203 ; -73.178,62.283 -73.178,60.378 -72.543,59.743 -68.733,59.743 ; -73.178,64.823 -68.733,64.823 ; -71.273,67.998 -68.733,67.998 -66.828,66.093 -66.828,62.918 -67.463,62.283 -68.733,62.283 ; -71.273,70.538 -68.86,72.92 ; -68.733,52.123 -68.098,52.123 ; -66.066,52.092 -66.066,60.728 -65.304,61.49 -65.304,68.252 ; -65.558,70.538 -64.288,70.538 -63.018,69.268 -63.018,66.728 -63.653,66.093 ; -23.094,10.594 -22.92,9.832 ; -4.394,10.594 -4.22,9.832
  BottomLayer w0.8: -68.86,72.92 -62.256,72.92 -60.986,71.904 -60.986,65.046 -61.113,64.569 ; -10.654,84.966 -10.654,85.474 ; -3.034,85.474 -3.034,88.776
  BottomLayer w1: -61.113,62.283 -58.8,62.3 -58.8,66.9 ; -32.868,9.832 -27.92,9.832 ; -4.22,9.832 -1.268,9.832 ; 2.046,93.094 6.11,93.094 9.158,90.046 9.158,79.632 ; 2.046,95.634 6.618,95.634 11.698,90.554 11.698,84.712 ; 6.11,95.634 6.11,97.92 ; 13.73,97.92 13.73,93.094 17.286,93.094 ; 34.812,125.352 38.114,125.352 38.114,128.908 38.114,131.702 ; 40.908,131.702 38.114,131.702 ; 41.924,121.288 44.21,121.288 ; 46.75,121.288 49.036,121.288 49.036,128.4 49.036,131.702 38.114,131.702 ; 51.576,122.05 51.576,128.4
  other v1: -17.6,33.7 7.888,114.938
  other v2: -58.954,47.012 -58.954,49.552

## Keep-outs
KeepOutLayer:
  lines w0.8: -77.9,7.3 -77.9,136.9 101.2,136.9 101.2,7.3 -77.9,7.3

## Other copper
TopLayer:
  rectangle: 36.9,133 62.7,136.3
  rectangle: 68.1,127.1 70.4,136.3
  rectangle: 62.3,92.2 68.1,136.3
  rectangle: 30.494,127.892 42.8,130.432
  rectangle: 24.398,128.654 32.018,129.416
  rectangle: 20.334,127.638 24.398,129.416
  rectangle: 15.254,125.86 24.398,127.638
  rectangle: 24.398,123.574 31.51,124.844
  rectangle: 11.444,123.574 24.398,125.86
  rectangle: 9.412,120.272 11.444,125.86
  rectangle: 4.84,109.35 11.444,120.272
  rectangle: 44.464,124.336 53.862,126.368
  rectangle: 53.608,124.336 63.514,133.4
  rectangle: 24.652,105.4 28.208,119.256
  rectangle: 8.904,64.9 15,82.172
  rectangle: 13.476,64.9 25.414,68.202
  rectangle: 4.332,67.44 9.158,82.172
  rectangle: 4.332,86.998 15,95.634
  rectangle: 4.332,81.664 7.126,89.03
  rectangle: 51.83,68.964 56.148,79.886
  rectangle: 51.576,85.982 54.37,98.428
  rectangle: 24.652,85.982 28.462,99.444
  rectangle: 24.652,70.996 29.224,79.886
  rectangle: 27.954,65.154 53.1,102.238
  rectangle: 24.652,64.9 28.716,70.996
  rectangle: 53.1,64.9 63.514,79.886
  rectangle: 54.37,86.998 63.514,96.904
  rectangle: 57.418,79.124 63.514,87.76
  rectangle: 55.9,117.732 63.514,124.336
  rectangle: 48.274,117.732 55.64,119.51
  rectangle: 62.498,96.396 63.514,117.732
  rectangle: -77.3,85.7 -20.9,136.3
  rectangle: 76.7,16.5 81.2,33
  rectangle: 80.9,25.3 92,31.1
  rectangle: 74.9,28.6 78.2,34.9
  rectangle: 26.7,7.9 84.7,11.1
  rectangle: 84.6,7.9 95.8,10
  rectangle: 86.8,9.1 94.4,19.7
  rectangle: 84.7,10 87.1,11.1
  rectangle: 22.5,7.9 28.1,20.6
  rectangle: 22.5,20.4 25.4,39.3
  rectangle: 35.6,43.6 63.514,65.3
  rectangle: 50.2,34 63.5,46.5
  rectangle: 51.7,32.1 63.5,35.2
  rectangle: 70.4,128.2 78.9,131.1
  rectangle: 70.9,113.9 78.9,122.4
  rectangle: 74.6,122.3 78.9,136.3
  rectangle: 19.3,67.9 24.9,91.5
  rectangle: -1.4,7.9 24.4,12.1
  rectangle: 18.9,46.1 31.2,62.3
  rectangle: -77.3,22.2 -66.5,45.3
  rectangle: -77.3,44.7 -74.8,85.7
  rectangle: -74.8,80.8 -20.9,85.7
  rectangle: -66.8,7.9 -61.3,34
  rectangle: -72.8,7.9 -66.8,22.2
  rectangle: -77.3,7.9 -72.7,16.8
  rectangle: -61.8,7.9 -30.4,12.1
  rectangle: -62,11.9 -53.2,17.2
  rectangle: -61.6,30.7 -54.7,34
  rectangle: -49.1,19.3 -38.5,24.2
  rectangle: -40.8,12.5 -38.5,19.3
  rectangle: -40.3,24.2 -38.5,36.9
  rectangle: -38.8,30.6 -30.6,34.4
  rectangle: -20.9,134 37.1,136.3
  rectangle: -21.1,131.8 15.2,134.1
  rectangle: 27.8,10.7 29.1,15.4
  rectangle: -63.6,36.6 -57.6,45.4
  rectangle: -30.9,30 -25.1,42.5
  rectangle: -33.9,15.4 -27.9,30.8
  rectangle: -25.8,30 -9.3,38
  rectangle: -21.4,15.3 -17.3,30.3
  rectangle: -27.5,20 -20.8,25
  rectangle: -17.5,18.1 -9.7,25.5
  rectangle: -55.2,41.9 -37.6,69.1
  rectangle: -55.2,39.8 -47.4,41.9
  rectangle: -37.9,59.7 -18.1,65.1
  rectangle: -34.5,65 -19.1,70.9
  rectangle: -37.9,41.9 -18.1,59.7
  rectangle: -18.2,41.9 14.2,57.2
  rectangle: -10.6,26.5 21,43.9
  rectangle: -3.1,17.2 18,26.7
  rectangle: 2.1,13.6 21,17.5
  rectangle: 14.2,43.9 16.7,54.1
  rectangle: -1.3,60.3 6.5,64.8
  rectangle: -18.2,57.2 14.2,61.3
  rectangle: 6.4,61.1 14.2,62.5
  rectangle: 17.8,17.5 21,22.7
  rectangle: 32.7,116.7 42.2,121.7
  rectangle: 26.4,36.2 50.6,39.9
BottomLayer:
  rectangle: 74.9,32.5 78.1,114.3
  rectangle: 58.5,92.2 65.9,97.158
  rectangle: 68.7,113.9 78.9,122.7
  rectangle: 63.3,92.1 69.4,118.4
  rectangle: -77.3,45.1 -74.9,85.8
  rectangle: -53.55,7.9 -44.4,9.552
  rectangle: -44.406,32.412 -37.3,36.984
  rectangle: 12.206,122.558 16.778,124.336
  rectangle: 9.92,119.256 12.206,124.336
  rectangle: 4.586,102.238 12.206,120.526
  rectangle: -45.1,7.9 -32.468,12.3
  rectangle: -33.992,7.9 -30.5,26.316
  rectangle: -33.992,26.062 -30.5,34.444
  rectangle: -44.406,32.4 -30.6,34.444
  rectangle: 24.906,105.032 35.066,108.588
  rectangle: 30.748,110.366 37.86,116.462
  rectangle: 62.752,94.364 63.514,117.986
  rectangle: 22.62,122.558 30.8,125.098
  rectangle: 31.5,133.226 70.4,136.3
  rectangle: 16.524,122.558 22.874,133.734
  rectangle: 38.622,115.192 42.94,119.764
  rectangle: 53.608,124.336 57.418,133.226
  rectangle: 38.114,117.224 42.686,123.066
  rectangle: 17.794,131.956 31.51,136.3
  rectangle: 30.748,128.908 36.082,135
  rectangle: 30.748,123.066 33.034,128.5
  rectangle: 30.748,115.192 38.876,123.066
  rectangle: 24.7,64.9 53.354,90.046
  rectangle: -53.804,9.298 -44.406,12.854
  rectangle: -19.1,130.432 18.556,136.3
  rectangle: -32.722,34.19 -30.5,42.5
  rectangle: -60.154,30.888 -56.598,42.064
  rectangle: -60.154,37.492 -47.454,43.8
  rectangle: -66.828,42.694 -63.018,46.758
  rectangle: -66.828,45.742 -63.526,50.568
  rectangle: -64.288,45.742 -63.018,62.76
  rectangle: -45.9,20.2 -41.104,28.348
  rectangle: -62.4,7.9 -53.296,16.918
  rectangle: 45.226,64.9 59.6,97.158
  rectangle: -77.3,30.8 -56.3,45.4
  rectangle: 7.38,64.9 13.2,82.172
  rectangle: 55.64,117.986 69.4,133.48
  rectangle: 42.94,117.732 63.514,119.002
  rectangle: 24.652,67.948 53.1,93.094
  rectangle: 24.652,91.062 53.3,108.588
  rectangle: 26.176,110.366 30.748,122.812
  rectangle: -77.3,85.7 -18.8,136.3
  rectangle: -75.8,81.6 -60.7,86.7
  rectangle: -72.8,7.9 -61.4,30.8
  rectangle: -77.3,7.9 -72.8,16.8
  rectangle: -77.3,22.2 -72.7,30.8
  rectangle: -1.9,62.6 8.3,65
  rectangle: 85.5,7.9 95.8,19.8
  rectangle: 25.3,7.9 52.7,15.4
  rectangle: 51.8,7.9 85.7,12.4
  rectangle: 31.1,36.2 48.4,39.9
  rectangle: 18.1,49.7 62,56.6
  rectangle: 55.8,37.3 62,49.9
  rectangle: 18.1,46.1 37.8,50
  rectangle: -2,7.9 27.6,10.9
  rectangle: 25.3,15.3 28.1,20.6
  rectangle: -30.5,20.1 -27.5,42.5
  rectangle: -21.2,12.6 -17.7,37.8
  rectangle: -27.6,30 -25.2,42.5
  rectangle: -30.5,12.7 -29.2,20.1
  rectangle: -27.8,20.1 -24.9,25
  rectangle: -18.5,30.1 -14.2,37.8
  rectangle: -18,18.1 -9.8,25.9
  rectangle: -29.5,12.7 -27.6,17.6
  rectangle: -19.5,122.2 -13,130.7
  rectangle: -13,126.8 -6.5,130.7
  rectangle: -53.5,44.9 -10.9,63.3
  rectangle: -57.1,43.8 -47.454,51.4
  rectangle: -32.3,62.6 -10.9,65.2
  rectangle: -48.2,40.4 -39.5,45.2
  rectangle: -11.3,41.7 13.1,61.3
  rectangle: -1.9,60.3 13.1,65
  rectangle: -15,41.7 -11,45.5
  rectangle: -10.5,26.5 21.5,42.1
  rectangle: 12.7,42.1 21.5,54
  rectangle: -3.1,15.8 18,26.6
  rectangle: 0.2,12.6 23.6,22.7
  rectangle: -37.5,40.8 -25.2,42.8
  rectangle: 21.3,26.5 24.4,37.7

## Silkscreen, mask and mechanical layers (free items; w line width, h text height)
TopOverlay:
  lines w0.254: -11.62,-8.568 -2.1,-8.568 -2.1,11.432 -11.62,11.432 ; -7.1,-8.568 -16.62,-8.568 -16.62,11.432 -7.1,11.432 ; 26.216,65.048 54.216,65.048 ; 26.278,65.118 26.278,105.118 ; 54.416,65.048 54.416,93.048 ; -60.24,79.76 -60.24,136.76 -20.24,136.76 -20.24,79.76 -60.24,79.76 ; -30.32,-8.568 -20.8,-8.568 -20.8,11.432 -30.32,11.432 -30.32,-8.568 ; 18.556,129.67 26.43,132.21 26.43,126.876 18.556,129.67 ; 26.416,80.248 54.416,80.248 54.416,97.848 50.716,105.248 26.416,105.248 26.416,80.248 ; 71.3,33.82 91.3,33.82 91.3,43.82 71.3,43.82 71.3,33.82 ; 71.3,45.32 91.3,45.32 91.3,55.32 71.3,55.32 71.3,45.32 ; 71.3,56.52 91.3,56.52 91.3,66.52 71.3,66.52 71.3,56.52 ; 71.3,68.02 91.3,68.02 91.3,78.02 71.3,78.02 71.3,68.02 ; 71.3,79.22 91.3,79.22 91.3,89.22 71.3,89.22 71.3,79.22 ; 71.3,90.72 91.3,90.72 91.3,100.72 71.3,100.72 71.3,90.72 ; 71.3,102.12 91.3,102.12 91.3,112.12 71.3,112.12 71.3,102.12 ; 71.3,124.82 91.3,124.82 91.3,134.82 71.3,134.82 71.3,124.82 ; 97,8.4 97,48.4 117,48.4 117,8.4 97,8.4 ; 97.2,51.5 97.2,91.5 117.2,91.5 117.2,51.5 97.2,51.5 ; 97.3,94.6 97.3,134.6 117.3,134.6 117.3,94.6 97.3,94.6
  text "PR1" at 20.2,132.4 h1
  text "+12V" at -2.1,130.7 h0.7
  text "N.O." at 84.8,125.5 h1
  text "GND" at -12.1,124.8 h0.7
  text "REL8" at 93.2,124.7 h1 r90
  text "UCC" at -5.574,114.176 h0.7
  text "MISO" at -14.21,113.922 h0.7
  text "SCK" at -13.442,111.398 h0.7
  text "MOSI" at -5.574,111.382 h0.7
  text "RES" at -13.442,108.858 h0.7
  text "GND" at -5.828,108.842 h0.7
  text "VSS -> GND" at 42.05,103.718 h0.8 r270
  text "VSS2 -> GND" at 34.442,103.694 h0.8 r270
  text "SCLK -> SCK" at 37.042,103.694 h0.8 r270
  text "VDD -> 3.3V" at 39.742,103.694 h0.8 r270
  text "DI -> MOSI" at 44.642,103.694 h0.8 r270
  text "CS -> SS" at 47.042,103.694 h0.8 r270
  text "DO -> MISO" at 31.742,103.594 h0.8 r270
  text "N.O." at 84.8,102.9 h1
  text "REL7" at 93.2,102 h1 r90
  text "NE-4110S" at -62.9,98 h1.6 r90
  text "N.O." at 84.8,91.5 h1
  text "REL6" at 93.2,90.6 h1 r90
  text "Ready" at -47,80.7 h0.8 r270
  text "N.O." at 84.7,80 h1
  text "100M" at -49.7,79.7 h0.8 r270
  text "RES" at -44.6,79.3 h0.8 r270
  text "TxD" at -24.3,79.3 h0.8 r270
  text "+5V" at -57.4,79.2 h0.8 r270
  text "+5V" at -54.8,79.2 h0.8 r270
  text "GND" at -26.8,79.2 h0.8 r270
  text "10M" at -52.2,79.1 h0.8 r270
  text "REL5" at 93.2,79.1 h1 r90
  text "SD/MMC" at 56.8,77.1 h2 r270
  text "GND" at -57.2,70.9 h0.8 r270
  text "GND" at -54.8,70.9 h0.8 r270
  text "RxD" at -23.7,70.8 h0.8 r270
  text "N.O." at 84.8,68.8 h1
  text "REL4" at 93.2,67.9 h1 r90
  text "www.frigg-tronic.pl" at -42.7,58.6 h1.6
  text "N.O." at 84.8,57.3 h1
  text "REL3" at 93.2,56.4 h1 r90
  text "Ethernet Controller" at -43,53.5 h1.8
  text "Tx" at -74.9,49.5 h0.7
  text "Rx" at -74.7,46.9 h0.7
  text "N.O." at 84.8,45.9 h1
  text "REL2" at 93.1,45.3 h1 r90
  text "L3" at -19.4,42.5 h1.2
  text "U4" at -51,35.7 h1.2
  text "N.O." at 84.8,34.4 h1
  text "REL1" at 93.1,33.8 h1 r90
  text "+9-12V" at -25.6,12.2 h1
  text "DATA" at -16.1,12.2 h1
  text "+5V" at -10.9,12.2 h1
  text "GND" at -29.19,12.118 h1
  text "GND" at -5.4,12.1 h1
